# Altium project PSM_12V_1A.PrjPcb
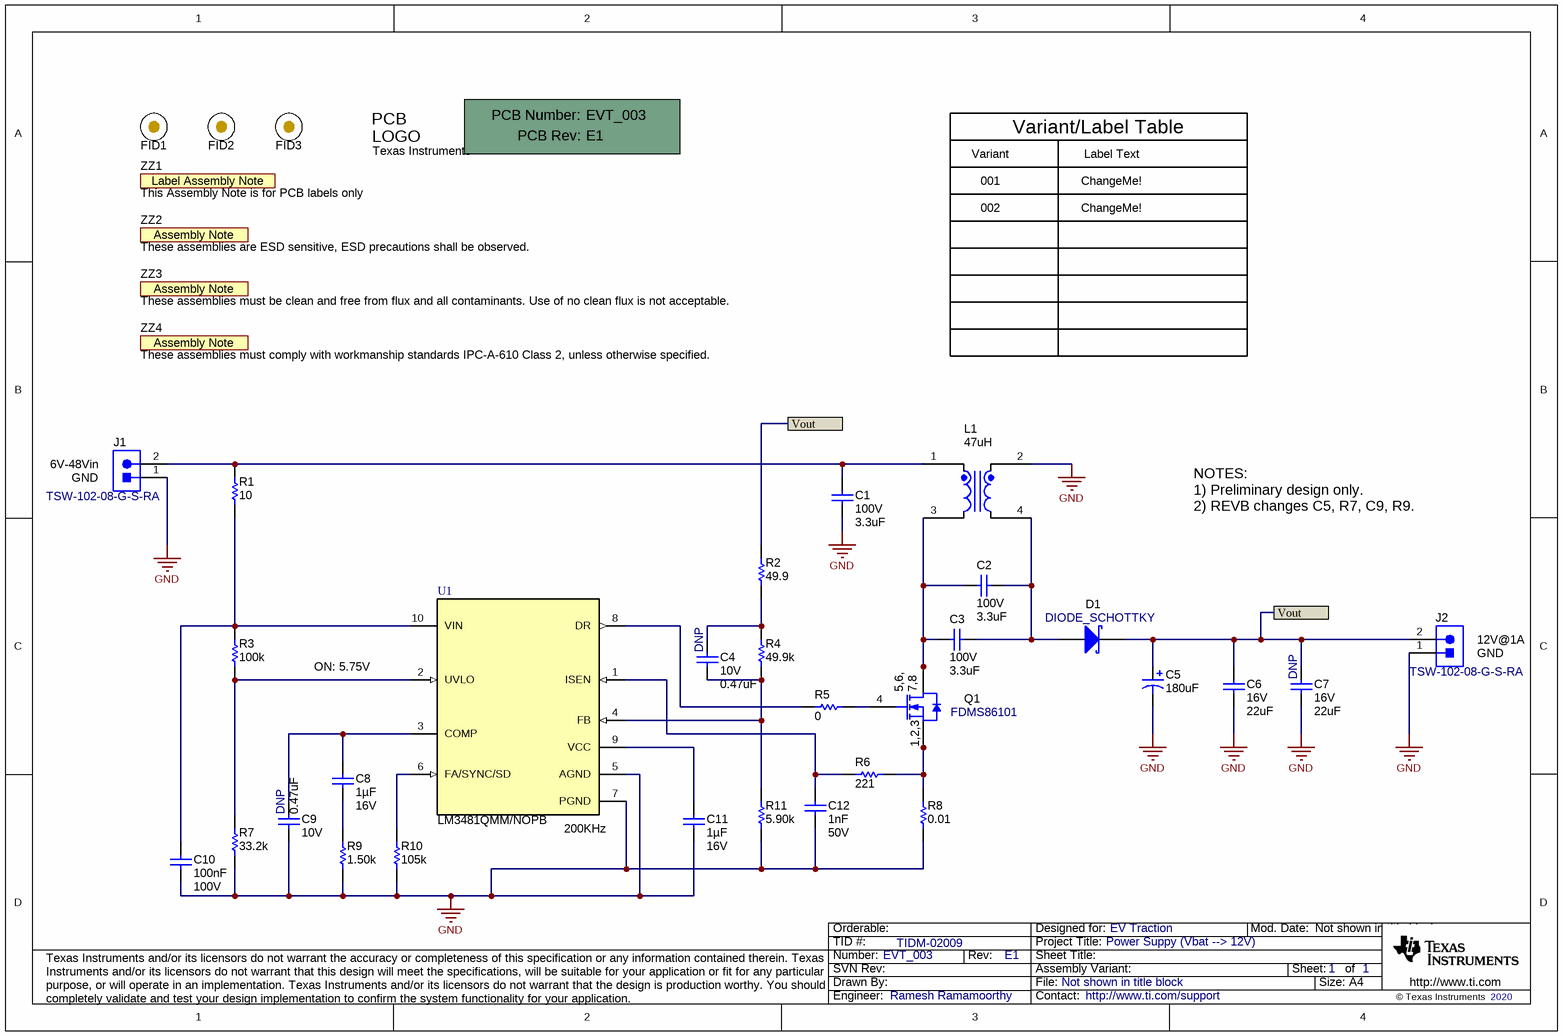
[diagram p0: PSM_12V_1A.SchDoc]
CopyrightYear: 2020; PCB_Layout: Ramesh Ramamoorthy; PCB_Rev: E1; PRJ_Customer: EV Traction; PRJ_Engineer: Ramesh Ramamoorthy; PRJ_Number: EVT_003; PRJ_Title: Power Suppy (Vbat --> 12V); SCH_Rev: E1; TechSupport: http://www.ti.com/support; TID: TIDM-02009
1 sheet, 38 parts. Net scope: flat (ports and power ports of the same name join across sheets).
Board file: PSM_12V_1A.PcbDoc

## Sheet PSM_12V_1A.SchDoc
size A4; Date: Not shown in title block; ApprovedBy: Not shown in title block; CheckedBy: Not shown in title block; Author: Not shown in title block; CompanyName: Not shown in title block; Engineer: Not shown in title block; Organization: Not shown in title block; Address1: Not shown in title block; Address2: Not shown in title block; Address3: Not shown in title block; Address4: Not shown in title block; DocumentNumber: 1; Revision: Use project parameter SCH_Rev; SheetNumber: 1; SheetTotal: 1; PageSetup: Record=PageOptions¦CenterHorizontal=True¦CenterVertical=True¦PrintScale=1.00¦XCorrection=1.00¦YCorrection=1.00¦PrintKind=0¦BorderSize=5000000¦LeftOffset=0¦BottomOffset=0¦Orientation=2¦PaperLength=1000¦PaperWidth=1000¦Scale=100¦PaperSource=15¦PrintQuality=600¦MediaType=1¦DitherType=10¦PaperKind=Letter¦PrintScaleMode=1

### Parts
!PCB1  Printed Circuit Board  (value not drawn)  (mechanical)
C1  VDC_V: 100V  ValueDisplayed: 3.3uF  [1210]  (hidden comment: C3225X7S2A335M200AB)
C2  VDC_V: 100V  ValueDisplayed: 3.3uF  [1210]  (hidden comment: C3225X7S2A335M200AB)
C3  VDC_V: 100V  ValueDisplayed: 3.3uF  [1210]  (hidden comment: C3225X7S2A335M200AB)
C4  VDC_V: 10V  ValueDisplayed: 0.47uF  [0603]  (hidden comment: C0603C474K8PACTU)
C5  ValueDisplayed: 180uF  [SVPF_E12]  (hidden comment: 25SVPF180M)
C6  VDC_V: 16V  ValueDisplayed: 22uF  [1206_190]  (hidden comment: EMK316BB7226ML-T)
C7  VDC_V: 16V  ValueDisplayed: 22uF  [1206_190]  (hidden comment: EMK316BB7226ML-T)
C8  Cap_F: 1µF  VDC_V: 16V  [0603]  (hidden comment: C1608X7R1C105K080AC)
C9  VDC_V: 10V  ValueDisplayed: 0.47uF  [0603]  (hidden comment: C0603C474K8PACTU)
C10  Cap_F: 100nF  VDC_V: 100V  [0805_HV]  (hidden comment: C2012X7R2A104K125AA)
C11  Cap_F: 1µF  VDC_V: 16V  [0603]  (hidden comment: C1608X7R1C105K080AC)
C12  Cap_F: 1nF  VDC_V: 50V  [0603]  (hidden comment: C0603X102K5RACTU)
D1  DIODE_SCHOTTKY  [SMC]
FID1  Fiducial  [Fiducial10-20]  (value not drawn)
FID2  Fiducial  [Fiducial10-20]  (value not drawn)
FID3  Fiducial  [Fiducial10-20]  (value not drawn)
J1  TSW-102-08-G-S-RA  [TSW-102-08-G-S-RA]
J2  TSW-102-08-G-S-RA  [TSW-102-08-G-S-RA]
L1  value 47uH  [IND_MSD1583]  (hidden comment: INDUCTOR_COUPLED_13_24)
Logo1  Texas Instruments  [TI_Symbol_Overlay_Small]  (no BOM)
Q1  FDMS86101  [TRANS_Fairchild_PQFN08A]
R1  value 10  [0603]  (hidden comment: Resistor)
R2  value 49.9  [0603]  (hidden comment: Resistor)
R3  value 100k  [0603]  (hidden comment: Resistor)
R4  value 49.9k  [0603]  (hidden comment: Resistor)
R5  value 0  [0603]  (hidden comment: Resistor)
R6  value 221  [0603]  (hidden comment: Resistor)
R7  value 33.2k  [0603]  (hidden comment: Resistor)
R8  value 0.01  [1206]  (hidden comment: Resistor)
R9  value 1.50k  [0603]  (hidden comment: Resistor)
R10  value 105k  [0603]  (hidden comment: Resistor)
R11  value 5.90k  [0603]  (hidden comment: Resistor)
U1  LM3481QMM/NOPB  [DGS0010A_N]
ZZ1  This Assembly Note is for PCB labels only  [AssemblyNoteLabel]  (no BOM)
ZZ2  These assemblies are ESD sensitive, ESD precautions shall be observed.  [AssemblyNote]  (no BOM)
ZZ3  These assemblies must be clean and free from flux and all contaminants. Use of no clean flux is not acceptable.  [AssemblyNote]  (no BOM)
ZZ4  These assemblies must comply with workmanship standards IPC-A-610 Class 2, unless otherwise specified.  [AssemblyNote]  (no BOM)

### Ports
Vout

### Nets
GND: C1.2 C5.2(-) C6.2 C7.2 C9.2 C10.2 C11.2 C12.2 J1.1 J2.1 L1.2 R7.1 R8.1 R9.1 R10.1 R11.1 U1.5(AGND) U1.7(PGND)
Vout: C5.1(+) C6.1 C7.1 D1.1(K) J2.2 R2.2 ; port Vout
NetC1_1: C1.1 J1.2 L1.1 R1.2
NetC2_1: C2.1 C3.1 L1.3 Q1.5(D) Q1.6(D) Q1.7(D) Q1.8(D)
NetC2_2: C2.2 C3.2 D1.2(A) L1.4
NetC4_1: C4.1 R2.1 R4.2
NetC4_2: C4.2 R4.1 R11.2 U1.4(FB)
NetC8_1: C8.1 C9.1 U1.3(COMP)
NetC8_2: C8.2 R9.2
NetC10_1: C10.1 R1.1 R3.2 U1.10(VIN)
NetC11_1: C11.1 U1.9(VCC)
NetC12_1: C12.1 R6.2 U1.1(ISEN)
NetQ1_1: Q1.1(S) Q1.2(S) Q1.3(S) R6.1 R8.2
NetQ1_4: Q1.4(G) R5.2
NetR3_1: R3.1 R7.2 U1.2(UVLO)
NetR5_1: R5.1 U1.8(DR)
NetR10_2: R10.2 U1.6(FA/SYNC/SD)

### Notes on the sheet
- Variant
- 001
- Variant/Label Table
- Label Text
- ChangeMe!
- 002
- (near J1) 6V-48Vin
- (near J1) GND
- NOTES:
  1) Preliminary design only.
  2) REVB changes C5, R7, C9, R9.
- (near C4) DNP
- (near J2) 12V@1A
- (near J2) GND
- ON: 5.75V
- (near C7) DNP
- (near C9) DNP
- (near U1) 200KHz

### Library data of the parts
!PCB1 = CMP-0003618-2: Manufacturer: Any; PartNumber: EVT_003
C1-C3 = CMP-0009133-1: CAP, CERM, 3.3 uF, 100 V, +/- 20%, X7S, 1210; Manufacturer: TDK; TaMin_C: -55°C; Polarized: N; SizeAreaWB_mm2: 14.7; Value1: Unknown; U/M: EA; Value: 3.3uF; TaMax_C: 125°C; SizeZ_mm: 1.35; SizeX_mm: 3.2; SizeY_mm: 2.5; SizeArea_mm2: 8; Cap_F: 3.3µF; AEC Category: Q200
C4 C9 = CMP-0006945-5: CAP, CERM, 0.47 uF, 10 V, +/- 10%, X5R, 0603; Manufacturer: Kemet; TaMin_C: -55°C; Polarized: N; SizeAreaWB_mm2: 4.68; Value1: Unknown; U/M: EA; Value: 0.47uF; TaMax_C: 85°C; SizeZ_mm: 1; SizeX_mm: 1.6; SizeY_mm: 0.8; SizeArea_mm2: 1.28; Cap_F: 470nF; AEC Category: Q200
C5 = CMP-0012118-3: CAP, Aluminum Polymer, 180 uF, 25 V, +/- 20%, 0.016 ohm, 2-Pin SMD, Body 8.3 x 8.3 mm, Height 12 mm SMD; Manufacturer: Panasonic; Polarized: Y; CompType: Capacitor; Value: 180uF; Cap_F: 180µF; VDC_V: 25V; ESR_ohm: 0.016; IRMS_A: 4.65A; TaMin_C: -55°C; TaMax_C: 105°C; Cap_Case: 8.0x11.9; AEC Category: Q200
C6 C7 = CMP-0008805-2: CAP, CERM, 22 uF, 16 V, +/- 20%, X7R, 1206_190; Manufacturer: Taiyo Yuden; TaMin_C: -55°C; Polarized: N; SizeAreaWB_mm2: 10.92; Value1: Unknown; U/M: EA; Value: 22uF; TaMax_C: 125°C; SizeZ_mm: 1.9; SizeX_mm: 3.2; SizeY_mm: 1.6; Cap_Case: 1206; SizeArea_mm2: 5.12; Cap_F: 22µF; AEC Category: Q200
C8 C11 = CMP-0007037-4: CAP, CERM, 1 uF, 16 V, +/- 10%, X7R, 0603; Manufacturer: TDK; TaMin_C: -55°C; ESR_ohm: 5.7m; Polarized: N; SizeAreaWB_mm2: 4.68; Value1: 0.0057 ohm; U/M: EA; Value: 1uF; TaMax_C: 125°C; SizeZ_mm: 1; SizeX_mm: 1.6; SizeY_mm: 0.8; SizeArea_mm2: 1.28; AEC Category: Q200
C10 = CMP-0007886-2: CAP, CERM, 0.1 uF, 100 V, +/- 10%, X7R, 0805; Manufacturer: TDK; TaMin_C: -55°C; ESR_ohm: 0.020726; Polarized: N; SizeAreaWB_mm2: 6.75; Value1: 0.020726 ohm; U/M: EA; Value: 0.1uF; TaMax_C: 125°C; SizeZ_mm: 1.45; SizeX_mm: 2; SizeY_mm: 1.25; Cap_Case: 0805; SizeArea_mm2: 2.5; IRMS_A: 1.456A; AEC Category: Q200
C12 = CMP-0006976-5: CAP, CERM, 1000 pF, 50 V, +/- 10%, X7R, 0603; Manufacturer: Kemet; TaMin_C: -55°C; Polarized: N; SizeAreaWB_mm2: 4.68; Value1: Unknown; U/M: EA; Value: 1000pF; TaMax_C: 125°C; SizeZ_mm: 1; SizeX_mm: 1.6; SizeY_mm: 0.8; SizeArea_mm2: 1.28; AEC Category: Q200
D1 = CMP-0028531-2: Diode, Schottky, 100 V, 3 A, SMC; PartNumber: MBRS3100T3G; Manufacturer: ON Semiconductor; Value: 100V; Vf_V: 620mV; Io_A: 3A; Value2: 0.62V; TJmax_C: 150°C; RJC_CperW: 11; AEC Category: Q101; Green_Lifecycle: Active; Green_REACh: Passed; SizeArea_mm2: 50.5686; SizeAreaWB_mm2: 83.2686; SizeX_mm: 8.13; SizeY_mm: 6.22; SizeZ_mm: 2.6
FID1-FID3 = CMP-0077181-1: Fiducial mark.  There is nothing to buy or mount.
J1 J2 = CMP-0055976-1: Header, 100mil, 2x1, Gold, R/A, TH; Manufacturer: Samtec; Cert_VDE: N; CNHeader: FALSE; Current_A: 6.3A; Green_Lifecycle: Active; Gender: Male; Cert_CSA: Y; Green_REACh: Passed; Voltage_V: 550V; Row_Count: 1; Pitch_mm: 2.54
L1 = CMP-0076818-2: Coupled inductor, 47 µH, 6.7 A, 0.1 ohm, SMD; Manufacturer: Coilcraft; PartNumber: MSD1583-473MEB; Ind_H: 47µH; DCR_ohm: 0.1; AEC Category: Q200; AEC Qualified: N
Logo1 = CMP-0074838-1: Texas Instrument Corporate Signature; SymbolCreator: a0412235; Lib Reference: TI_Logo; Library Reference: Logo
Q1 = CMP-0000984-1: MOSFET, N-CH, 100 V, 60 A, PQFN08A; Alternate Manufacturer: None; Manufacturer: Fairchild Semiconductor; SizeZ_mm: 1.1; ChType: N; Value2: 39 nC; VdsMax_V: 100V; SizeX_mm: 5; SizeAreaWB_mm2: 56; SizeY_mm: 6; Vgs_V: 20V; QgTyp_nC: 39; Value: 100V; SizeArea_mm2: 30; AEC Category: Q101; IdsMax_A: 60A; U/M: EA
R1 = CMP-0025703-4: RES, 10, 5%, 0.1 W, AEC-Q200 Grade 0, 0603; PartNumber: CRCW060310R0JNEA; Manufacturer: Vishay-Dale; Value_Code: 10R0; Power_W: 100mW; Value2: 0.1W; VDC_V: 75V; TempCo: 200 ppm/C; EIA_Code: E24; AEC Category: Q200; AEC Grade: 0; AEC Qualified: Y; SizeArea_mm2: 1.28; SizeX_mm: 1.6; SizeY_mm: 0.8; SizeZ_mm: 1
R2 = CMP-0022448-4: RES, 49.9, 1%, 0.1 W, AEC-Q200 Grade 0, 0603; PartNumber: CRCW060349R9FKEA; Manufacturer: Vishay-Dale; Value_Code: 49R9; Power_W: 100mW; Value2: 0.1W; VDC_V: 75V; TempCo: 100 ppm/C; EIA_Code: E96; AEC Category: Q200; AEC Grade: 0; AEC Qualified: Y; SizeArea_mm2: 1.28; SizeX_mm: 1.6; SizeY_mm: 0.8; SizeZ_mm: 1
R3 = CMP-0021990-4: RES, 100 k, 1%, 0.1 W, AEC-Q200 Grade 0, 0603; PartNumber: CRCW0603100KFKEA; Manufacturer: Vishay-Dale; Power_W: 100mW; Value2: 0.1W; VDC_V: 75V; TempCo: 100 ppm/C; EIA_Code: E96; AEC Category: Q200; AEC Grade: 0; AEC Qualified: Y; SizeArea_mm2: 1.28; SizeX_mm: 1.6; SizeY_mm: 0.8; SizeZ_mm: 1
R4 = CMP-0022447-4: RES, 49.9 k, 1%, 0.1 W, AEC-Q200 Grade 0, 0603; PartNumber: CRCW060349K9FKEA; Manufacturer: Vishay-Dale; Value_Code: 49k9; Power_W: 100mW; Value2: 0.1W; VDC_V: 75V; TempCo: 100 ppm/C; EIA_Code: E96; AEC Category: Q200; AEC Grade: 0; AEC Qualified: Y; SizeArea_mm2: 1.28; SizeX_mm: 1.6; SizeY_mm: 0.8; SizeZ_mm: 1
R5 = CMP-0025697-4: RES, 0, 5%, 0.1 W, AEC-Q200 Grade 0, 0603; PartNumber: CRCW06030000Z0EA; Manufacturer: Vishay-Dale; Value_Code: 0000; Power_W: 100mW; Value2: 0.1W; VDC_V: 75V; TempCo: 200 ppm/C; EIA_Code: E24; AEC Category: Q200; AEC Qualified: Y; SizeArea_mm2: 1.28; SizeX_mm: 1.6; SizeY_mm: 0.8; SizeZ_mm: 1
R6 = CMP-0022217-5: RES, 221, 1%, 0.1 W, AEC-Q200 Grade 0, 0603; PartNumber: CRCW0603221RFKEA; Manufacturer: Vishay-Dale; Value_Code: 221R; Power_W: 100mW; Value2: 0.1W; VDC_V: 75V; TempCo: 100 ppm/C; EIA_Code: E96; AEC Category: Q200; AEC Grade: 0; AEC Qualified: Y; SizeArea_mm2: 1.28; SizeX_mm: 1.6; SizeY_mm: 0.8; SizeZ_mm: 1
R7 = CMP-0022339-4: RES, 33.2 k, 1%, 0.1 W, AEC-Q200 Grade 0, 0603; PartNumber: CRCW060333K2FKEA; Manufacturer: Vishay-Dale; Value_Code: 33k2; Power_W: 100mW; Value2: 0.1W; VDC_V: 75V; TempCo: 100 ppm/C; EIA_Code: E96; AEC Category: Q200; AEC Grade: 0; AEC Qualified: Y; SizeArea_mm2: 1.28; SizeX_mm: 1.6; SizeY_mm: 0.8; SizeZ_mm: 1
R8 = CMP-0017256-2: RES, 0.01, 1%, 0.5 W, 1206; PartNumber: CSR1206FK10L0; Manufacturer: Stackpole Electronics Inc; Value_Code: R010; Power_W: 500mW; Value2: 0.5W; TempCo: 100 ppm/C; EIA_Code: E96; U/M: EA; AEC Category: Q200; SizeArea_mm2: 5.12; SizeX_mm: 3.2; SizeY_mm: 1.6; SizeZ_mm: 1.35
R9 = CMP-0022126-4: RES, 1.50 k, 1%, 0.1 W, AEC-Q200 Grade 0, 0603; PartNumber: CRCW06031K50FKEA; Manufacturer: Vishay-Dale; Res_ohm: 1.5k; Value_Code: 1k50; Power_W: 100mW; Value2: 0.1W; VDC_V: 75V; TempCo: 100 ppm/C; EIA_Code: E96; AEC Category: Q200; AEC Grade: 0; AEC Qualified: Y; SizeArea_mm2: 1.28; SizeX_mm: 1.6; SizeY_mm: 0.8; SizeZ_mm: 1
R10 = CMP-0021994-4: RES, 105 k, 1%, 0.1 W, AEC-Q200 Grade 0, 0603; PartNumber: CRCW0603105KFKEA; Manufacturer: Vishay-Dale; Power_W: 100mW; Value2: 0.1W; VDC_V: 75V; TempCo: 100 ppm/C; EIA_Code: E96; AEC Category: Q200; AEC Grade: 0; AEC Qualified: Y; SizeArea_mm2: 1.28; SizeX_mm: 1.6; SizeY_mm: 0.8; SizeZ_mm: 1
R11 = CMP-0022515-4: RES, 5.90 k, 1%, 0.1 W, AEC-Q200 Grade 0, 0603; PartNumber: CRCW06035K90FKEA; Manufacturer: Vishay-Dale; Res_ohm: 5.9k; Value_Code: 5k90; Power_W: 100mW; Value2: 0.1W; VDC_V: 75V; TempCo: 100 ppm/C; EIA_Code: E96; AEC Category: Q200; AEC Grade: 0; AEC Qualified: Y; SizeArea_mm2: 1.28; SizeX_mm: 1.6; SizeY_mm: 0.8; SizeZ_mm: 1
U1 = CMP-0071928-2: High Efficiency Low-Side N-Channel Controller for Switching Regulators, AEC-Q100 Grade 1, 10-pin Mini SOIC, 1000 Reel; Manufacturer: Texas Instruments; Alternate PartNumber: LM3481QMMX/NOPB; CompType: IC; AEC Category: Q200; AEC Qualified: Y; SizeAreaWB_mm2: 23.6; SizeArea_mm2: 14.7; SizeX_mm: 4.9; SizeY_mm: 3; SizeZ_mm: 1.1
ZZ1 = CMP-0003616-3
ZZ2 = CMP-0077236-1
ZZ3 = CMP-0077237-1
ZZ4 = CMP-0077238-1

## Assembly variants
001: not fitted FID1 FID2 FID3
